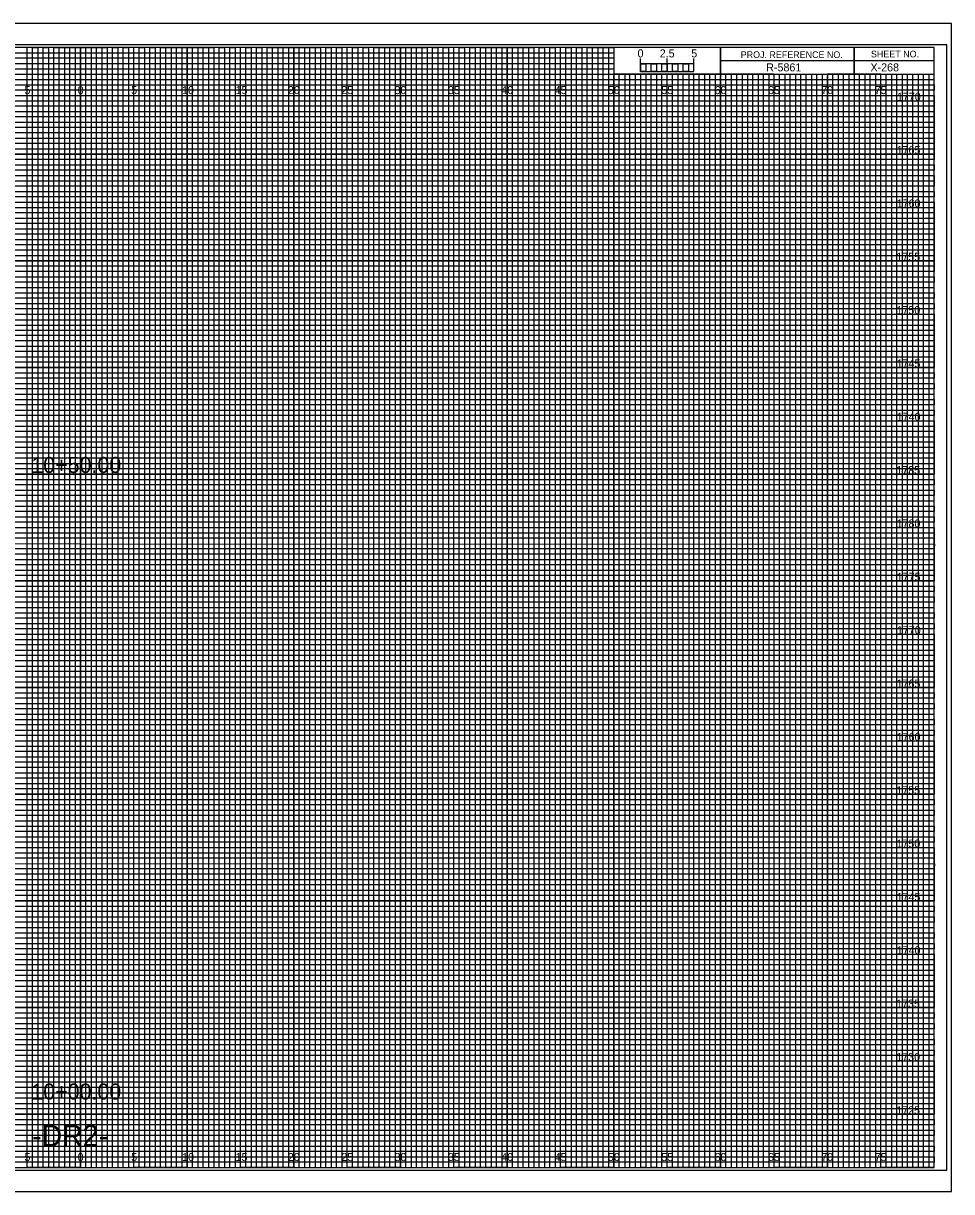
# Model space of a CAD drawing. Extents: x -7 to 162, y -2 to 217.
# Drawn here: x 74.6 to 161.7, y -2.3 to 107.3 of the extents above; entities that cross this region are included whole.
import ezdxf

# ---------------------------------------------------------------- set-up
doc = ezdxf.new("R2010")
doc.units = 0
for name, color, linetype in [('Prop XS Alignment Label', 7, 'Continuous'), ('Prop XS Bar Scale Labels', 7, 'Continuous'), ('Prop XS Elevation Labels', 7, 'Continuous'), ('Prop XS Offset Labels', 7, 'Continuous'), ('Prop XS Project Number', 7, 'Continuous'), ('Prop XS Sheet Number', 7, 'Continuous'), ('Prop XS Station Labels', 7, 'Continuous'), ('Sheet Cross Section CELL', 7, 'Continuous'), ('Sheet Cross Section Grid Major CELL', 7, 'Continuous'), ('Sheet Cross Section Grid Middle CELL', 7, 'Continuous'), ('Sheet Cross Section Grid Minor 1 CELL', 7, 'Continuous'), ('Sheet Cross Section Grid Minor 2 CELL', 7, 'Continuous'), ('Sheet Cross Section Scale CELL', 7, 'Continuous'), ('Sheet Cutting Line CELL', 7, 'Continuous'), ('Sheet DOT Grid CELL', 7, 'Continuous'), ('Sheet Plot Border Inside CELL', 7, 'Continuous'), ('Sheet Plot Border Outside CELL', 7, 'Continuous')]:
    doc.layers.add(name, color=color, linetype=linetype)

msp = doc.modelspace()

# ---------------------------------------------------------------- linework, layer by layer
at = {"layer": 'Sheet Cross Section CELL'}
for p, q in [((152.5, 105), (152.5, 102.5)), ((152.5, 102.5), (152.5, 105)), ((160, 103.75), (140, 103.75)), ((140, 103.75), (140, 102.5)), ((140, 102.5), (160, 102.5))]:
    msp.add_line(p, q, dxfattribs=at)
for points in [[(160, 105), (0, 105), (0, 0), (160, 0)], [(140, 105), (130, 105), (130, 102.52), (140, 102.52)], [(160, 105), (140, 105), (140, 102.5), (160, 102.5)]]:
    msp.add_lwpolyline(points, close=True, dxfattribs=at)
at = {"layer": 'Sheet Cross Section Grid Major CELL'}
for p, q in [((75, 105), (70, 105)), ((75, 0), (75, 105)), ((85, 105), (80, 105)), ((80, 105), (80, 0)), ((85, 0), (85, 105)), ((95, 105), (90, 105)), ((90, 105), (90, 0)), ((95, 0), (95, 105)), ((105, 105), (100, 105)), ((100, 105), (100, 0)), ((105, 0), (105, 105)), ((115, 105), (110, 105)), ((110, 105), (110, 0)), ((115, 0), (115, 105)), ((125, 105), (120, 105)), ((120, 105), (120, 0)), ((125, 0), (125, 105)), ((130, 105), (130, 0)), ((135, 0), (135, 102.5)), ((145, 102.5), (140, 102.5)), ((140, 102.5), (140, 0)), ((145, 0), (145, 102.5)), ((155, 102.5), (150, 102.5)), ((150, 102.5), (150, 0)), ((155, 0), (155, 102.5)), ((80, 0), (75, 0)), ((90, 0), (85, 0)), ((100, 0), (95, 0)), ((110, 0), (105, 0)), ((120, 0), (115, 0)), ((130, 0), (125, 0)), ((140, 0), (135, 0)), ((150, 0), (145, 0)), ((160, 0), (155, 0)), ((160, 0), (160, 0))]:
    msp.add_line(p, q, dxfattribs=at)
for points in [[(0, 100), (160, 100), (160, 95), (0, 95)], [(0, 90), (160, 90), (160, 85), (0, 85)], [(0, 80), (160, 80), (160, 75), (0, 75)], [(0, 70), (160, 70), (160, 65), (0, 65)], [(0, 60), (160, 60), (160, 55), (0, 55)], [(0, 50), (160, 50), (160, 45), (0, 45)], [(0, 40), (160, 40), (160, 35), (0, 35)], [(0, 30), (160, 30), (160, 25), (0, 25)], [(0, 20), (160, 20), (160, 15), (0, 15)], [(0, 10), (160, 10), (160, 5), (0, 5)]]:
    msp.add_lwpolyline(points, dxfattribs=at)
at = {"layer": 'Sheet Cross Section Grid Middle CELL'}
for points in [[(72.5, 0), (77.5, 0), (77.5, 105), (82.5, 105), (82.5, 0), (87.5, 0), (87.5, 105), (92.5, 105), (92.5, 0), (97.5, 0), (97.5, 105), (102.5, 105), (102.5, 0), (107.5, 0), (107.5, 105), (112.5, 105), (112.5, 0), (117.5, 0), (117.5, 105), (122.5, 105), (122.5, 0), (127.5, 0), (127.5, 105), (129.97, 105), (130, 105), (130, 102.5), (132.5, 102.5), (132.5, 0), (137.5, 0), (137.5, 102.5), (142.5, 102.5), (142.5, 0), (147.5, 0), (147.5, 102.5), (152.5, 102.5), (152.5, 0), (157.5, 0), (157.5, 102.5)], [(0, 102.5), (137.5, 102.5)], [(0, 92.5), (160, 92.5), (160, 97.5), (0, 97.5)], [(0, 82.5), (160, 82.5), (160, 87.5), (0, 87.5)], [(0, 72.5), (160, 72.5), (160, 77.5), (0, 77.5)], [(0, 62.5), (160, 62.5), (160, 67.5), (0, 67.5)], [(0, 52.5), (160, 52.5), (160, 57.5), (0, 57.5)], [(0, 42.5), (160, 42.5), (160, 47.5), (0, 47.5)], [(0, 32.5), (160, 32.5), (160, 37.5), (0, 37.5)], [(0, 22.5), (160, 22.5), (160, 27.5), (0, 27.5)], [(0, 12.5), (160, 12.5), (160, 17.5), (0, 17.5)], [(0, 2.5), (160, 2.5), (160, 7.5), (0, 7.5)]]:
    msp.add_lwpolyline(points, dxfattribs=at)
at = {"layer": 'Sheet Cross Section Grid Minor 1 CELL'}
for p, q in [((0, 104.5), (130, 104.5)), ((130, 104.5), (130, 103.99)), ((130, 103.99), (0, 103.99)), ((0, 103.5), (130, 103.5)), ((130, 102.95), (0, 102.95)), ((130, 103.5), (130, 102.95)), ((0, 102), (160, 102))]:
    msp.add_line(p, q, dxfattribs=at)
for points in [[(0, 101.5), (135, 101.5), (160, 101.5), (160, 101), (0, 101)], [(0, 100.5), (160, 100.5), (160, 99.5), (0, 99.5)], [(0, 99), (160, 99), (160, 98.5), (0, 98.49)], [(0, 98), (160, 98), (160, 97), (0, 97)], [(0, 96.5), (160, 96.5), (160, 96), (0, 96)], [(0, 95.5), (160, 95.5), (160, 94.5), (0, 94.5)], [(0, 94), (160, 94), (160, 93.5), (0, 93.5)], [(0, 93), (160, 93), (160, 92), (0, 92)], [(0, 91.5), (160, 91.5), (160, 91), (0, 91)], [(0, 90.5), (160, 90.5), (160, 89.5), (0, 89.5)], [(0, 89), (160, 89), (160, 88.5), (0, 88.5)], [(0, 88), (160, 88), (160, 86.98), (160, 86.5), (160, 86), (0, 86)], [(0, 87), (160, 87), (160, 86.5), (0, 86.5)], [(0, 85.5), (160, 85.5), (160, 84.5), (0, 84.52)], [(0, 84.52), (160, 84.5), (160, 84), (0, 84)], [(0, 83.5), (160, 83.5), (160, 83), (0, 83)], [(0, 82), (160, 82), (160, 81.5), (0, 81.5)], [(0, 81), (160, 81), (160, 80.5), (0, 80.5)], [(-0.04, 79.45), (160, 79.45), (160, 78.94), (-0.04, 78.94)], [(0, 78.5), (160, 78.5), (160, 78), (0, 78)], [(0, 77), (160, 77), (160, 76.5), (0, 76.5)], [(0, 76), (160, 76), (160, 75.5), (0, 75.5)], [(0, 74.5), (160, 74.5), (160, 74), (0, 74)], [(0, 73.5), (160, 73.5), (160, 73), (0, 73)], [(0, 72), (160, 72), (160, 71.5), (0, 71.5)], [(0, 71), (160, 71), (160, 70.5), (0, 70.5)], [(0, 69.5), (160, 69.5), (160, 68.99), (0, 69)], [(0, 68.5), (160, 68.5), (160, 68), (0, 68)], [(0, 67), (160, 67), (160, 66.5), (0, 66.5)], [(0, 66), (160, 66), (160, 65.5), (0, 65.5)], [(0, 64.5), (160, 64.5), (160, 64), (0, 64)], [(0, 63.5), (160, 63.5), (160, 63), (0, 63)], [(0, 62), (160, 62), (160, 61.5), (0, 61.5)], [(0, 61), (160, 61), (160, 60.5), (0, 60.5)], [(0, 59.5), (160, 59.5), (160, 59), (0, 59)], [(0, 58.5), (160.03, 58.45), (160, 58), (0, 58)], [(0, 57), (160, 57), (160, 56.5), (0, 56.5)], [(0, 56), (160, 56), (160, 55.5), (0, 55.5)], [(0, 54.5), (160, 54.5), (160, 54), (0, 54)], [(0, 53.5), (160, 53.5), (160, 53), (0, 53)], [(0, 52), (160, 52), (160, 51.5), (0, 51.5)], [(0, 51), (160, 51), (160, 50.5), (0, 50.5)], [(0, 49.5), (160, 49.5), (160, 49), (0, 49)], [(0, 48.5), (160, 48.5), (160, 48), (0, 48)], [(0, 47), (160, 47), (160, 46.5), (0, 46.5)], [(0, 46), (160, 46), (160, 45.5), (0, 45.5)], [(0, 44.5), (160, 44.5), (160, 44), (0, 44)], [(0, 43.5), (160, 43.5), (160, 43), (0, 43)], [(0, 42), (160, 42), (160, 41.5), (0, 41.5)], [(0, 41), (160, 41), (160, 40.5), (0, 40.5)], [(0, 39.5), (160, 39.5), (160, 38.99), (0, 39)], [(0, 38.5), (160, 38.5), (160, 38), (0, 38)], [(0, 37), (160, 37), (160, 36.5), (0, 36.5)], [(0, 36), (160, 36), (160, 35.5), (0, 35.5)], [(0, 34.5), (160, 34.5), (160, 34), (0, 34)], [(0, 33.5), (160, 33.5), (160, 33), (0, 33)], [(0, 32), (160, 32), (160, 31.5), (0, 31.5)], [(0, 31), (160, 31), (160, 30.5), (0, 30.5)], [(0, 29.5), (160, 29.5), (160, 29), (0, 29)], [(0, 28.5), (160.03, 28.46), (160, 28), (0, 28)], [(0, 27), (160, 27), (160, 26.5), (0, 26.5)], [(0, 26), (160, 26), (160, 25.5), (0, 25.5)], [(0, 24.5), (160, 24.5), (160, 24), (0, 24)], [(0, 23.5), (160, 23.5), (160, 23), (0, 23)], [(0, 22), (160, 22), (160, 21.5), (0, 21.5)], [(0, 21), (160, 21), (160, 20.5), (0, 20.5)], [(0, 19.5), (160, 19.5), (160, 19), (0, 19)], [(0, 18.5), (160, 18.5), (160, 18), (0, 18)], [(0, 17), (160, 17), (160, 16.5), (0, 16.5)], [(0, 16), (160, 16), (160, 15.5), (0, 15.5)], [(0, 14.5), (160, 14.5), (160, 14), (0, 14)], [(0, 13.5), (160, 13.5), (160, 13), (0, 13)], [(0, 12), (160, 12), (160, 11.5), (0, 11.5)], [(0, 11), (160, 11), (160, 10.5), (0, 10.5)], [(0, 9.5), (160, 9.5), (160, 9), (0, 9)], [(0, 8.5), (160, 8.5), (160, 8), (0, 8)], [(0, 7), (160, 7), (160, 6.5), (0, 6.5)], [(0, 6), (160, 6), (160, 5.5), (0, 5.5)], [(0, 4.5), (160, 4.5), (160, 4), (0, 4)], [(0, 3.5), (160, 3.5), (160, 3), (0, 3)], [(0, 2), (160, 2), (160, 1.5), (0, 1.5)], [(0, 1), (160, 1), (160, 0.5), (0, 0.5)]]:
    msp.add_lwpolyline(points, dxfattribs=at)
at = {"layer": 'Sheet Cross Section Grid Minor 2 CELL'}
for p, q in [((133.5, 102.5), (133, 102.5)), ((133, 102.5), (133, 0)), ((133.5, 0), (133.5, 102.5)), ((134.5, 102.5), (134, 102.5)), ((134, 102.5), (134, 0)), ((134.5, 0), (134.5, 102.5)), ((133, 0), (132.5, 0)), ((134, 0), (133.5, 0))]:
    msp.add_line(p, q, dxfattribs=at)
for points in [[(75, 0), (75.5, 0), (75.5, 105), (76, 105), (76, 0)], [(76, 0), (76.5, 0), (76.5, 105), (77, 105), (77, 0)], [(77.5, 0), (78, 0), (78, 105), (78.5, 105), (78.5, 0)], [(78.5, 0), (79, 0), (79, 105), (79.5, 105), (79.5, 0)], [(80, 0), (80.5, 0), (80.5, 105), (81, 105), (81, 0)], [(81, 0), (81.5, 0), (81.5, 105), (82, 105), (82, 0)], [(82.5, 0), (83, 0), (83, 105), (83.5, 105), (83.5, 0)], [(83.5, 0), (84, 0), (84, 105), (84.5, 105), (84.5, 0)], [(85, 0), (85.5, 0), (85.5, 105), (86, 105), (86, 0)], [(86, 0), (86.5, 0), (86.5, 105), (87, 105), (87, 0)], [(87.5, 0), (88, 0), (88, 105), (88.5, 105), (88.5, 0)], [(88.5, 0), (89, 0), (89, 105), (89.5, 105), (89.5, 0)], [(90, 0), (90.5, 0), (90.5, 105), (91, 105), (91, 0)], [(91, 0), (91.5, 0), (91.5, 105), (92, 105), (92, 0)], [(92.5, 0), (93, 0), (93, 105), (93.5, 105), (93.5, 0)], [(93.5, 0), (94, 0), (94, 105), (94.5, 105), (94.5, 0)], [(95, 0), (95.5, 0), (95.5, 105), (96, 105), (96, 0)], [(96, 0), (96.5, 0), (96.5, 105), (97, 105), (97, 0)], [(97.5, 0), (98, 0), (98, 105), (98.5, 105), (98.5, 0)], [(98.5, 0), (99, 0), (99, 105), (99.5, 105), (99.5, 0)], [(100, 0), (100.5, 0), (100.5, 105), (101, 105), (101, 0)], [(101, 0), (101.5, 0), (101.5, 105), (102, 105), (102, 0)], [(102.5, 0), (103, 0), (103, 105), (103.5, 105), (103.5, 0)], [(103.5, 0), (104, 0), (104, 105), (104.5, 105), (104.5, 0)], [(105, 0), (105.5, 0), (105.5, 105), (106, 105), (106, 0)], [(106, 0), (106.5, 0), (106.5, 105), (107, 105), (107, 0)], [(107.5, 0), (108, 0), (108, 105), (108.5, 105), (108.5, 0)], [(108.5, 0), (109, 0), (109, 105), (109.5, 105), (109.5, 0)], [(110, 0), (110.5, 0), (110.5, 105), (111, 105), (111, 0)], [(111, 0), (111.5, 0), (111.5, 105), (112, 105), (112, 0)], [(112.5, 0), (113, 0), (113, 105), (113.5, 105), (113.5, 0)], [(113.5, 0), (114, 0), (114, 105), (114.5, 105), (114.5, 0)], [(115, 0), (115.5, 0), (115.5, 105), (116, 105), (116, 0)], [(116, 0), (116.5, 0), (116.5, 105), (117, 105), (117, 0)], [(117.5, 0), (118, 0), (118, 105), (118.5, 105), (118.5, 0)], [(118.5, 0), (119, 0), (119, 105), (119.5, 105), (119.5, 0)], [(120, 0), (120.5, 0), (120.5, 105), (121, 105), (121, 0)], [(121, 0), (121.5, 0), (121.5, 105), (122, 105), (122, 0)], [(122.5, 0), (123, 0), (123, 105), (123.5, 105), (123.5, 0)], [(123.5, 0), (124, 0), (124, 105), (124.5, 105), (124.5, 0)], [(125, 0), (125.5, 0), (125.5, 105), (126, 105), (126, 0)], [(126, 0), (126.5, 0), (126.5, 105), (127, 105), (127, 0)], [(127.5, 0), (128, 0), (128, 105), (128.5, 105), (128.5, 0)], [(128.5, 0), (129, 0), (129, 105), (129.5, 105), (129.5, 0)], [(130, 0), (130.5, 0), (130.5, 102.5), (131.01, 102.5), (131.01, 0)], [(131, 0), (131.5, 0), (131.5, 102.5), (132, 102.5), (132, 0)], [(135, 0), (135.49, 0), (135.49, 102.5), (136, 102.5), (136, 0)], [(136, 0), (136.5, 0), (136.5, 102.5), (137.03, 102.5), (137.03, 0)], [(137.5, 0), (138, 0), (138, 102.5), (138.5, 102.5), (138.5, 0)], [(138.5, 0), (139, 0), (139, 102.5), (139.5, 102.5), (139.5, 0)], [(140, 0), (140.5, 0), (140.5, 102.5), (141, 102.5), (141, 0)], [(141, 0), (141.5, 0), (141.5, 102.5), (142, 102.5), (142, 0)], [(142.5, 0), (143, 0), (143, 102.5), (143.5, 102.5), (143.5, 0)], [(143.5, 0), (144, 0), (144, 102.5), (144.5, 102.5), (144.5, 0)], [(145, 0), (145.5, 0), (145.5, 102.5), (146, 102.5), (146, 0)], [(146, 0), (146.5, 0), (146.5, 102.5), (147, 102.5), (147, 0)], [(147.5, 0), (148, 0), (148, 102.5), (148.5, 102.5), (148.5, 0)], [(148.5, 0), (149, 0), (149, 102.5), (149.5, 102.5), (149.5, 0)], [(150, 0), (150.5, 0), (150.5, 102.5), (151, 102.5), (151, 0)], [(151, 0), (151.5, 0), (151.5, 102.5), (152, 102.5), (152, 0)], [(152.5, 0), (153, 0), (153, 102.5), (153.5, 102.5), (153.5, 0)], [(153.5, 0), (154, 0), (154, 102.5), (154.5, 102.5), (154.5, 0)], [(155, 0), (155.5, 0), (155.5, 102.5), (156, 102.5), (156, 0)], [(156, 0), (156.5, 0), (156.5, 102.5), (157, 102.5), (157, 0)], [(157.5, 0), (158, 0), (158, 102.5), (158.5, 102.5), (158.5, 0)], [(158.5, 0), (159, 0), (159, 102.5), (159.5, 102.5), (159.5, 0)]]:
    msp.add_lwpolyline(points, dxfattribs=at)
at = {"layer": 'Sheet Cross Section Scale CELL'}
for p, q in [((132.5, 102.75), (132.5, 103.95)), ((132.5, 103.45), (132.5, 103.95)), ((135, 102.75), (135, 103.95)), ((137.5, 102.75), (137.5, 103.95)), ((137.5, 103.45), (137.5, 103.95))]:
    msp.add_line(p, q, dxfattribs=at)
for points in [[(137.5, 103.45), (132.5, 103.45), (132.5, 102.75), (137.5, 102.75)], [(132.5, 103.45), (133, 103.45), (133, 102.75), (132.5, 102.75)], [(133.5, 103.45), (134, 103.45), (134, 102.75), (133.5, 102.75)], [(134.5, 103.45), (135, 103.45), (135, 102.75), (134.5, 102.75)], [(135.5, 103.45), (136, 103.45), (136, 102.75), (135.5, 102.75)], [(136.5, 103.45), (137, 103.45), (137, 102.75), (136.5, 102.75)]]:
    msp.add_lwpolyline(points, close=True, dxfattribs=at)
at = {"layer": 'Sheet Cutting Line CELL'}
for p, q in [((161.65, 107.25), (-6.7, 107.25)), ((-6.7, -2.25), (161.65, -2.25))]:
    msp.add_line(p, q, dxfattribs=at)
at = {"layer": 'Sheet DOT Grid CELL'}
for p, q in [((75, 0), (75, 105)), ((80, 0), (80, 105)), ((85, 0), (85, 105)), ((90, 0), (90, 105)), ((95, 0), (95, 105)), ((100, 0), (100, 105)), ((105, 0), (105, 105)), ((110, 0), (110, 105)), ((115, 0), (115, 105)), ((120, 0), (120, 105)), ((125, 0), (125, 105)), ((130, 0), (130, 102.34)), ((135, 0), (135, 102.34)), ((140, 0), (140, 102.34)), ((145, 0), (145, 102.34)), ((150, 0), (150, 102.34)), ((155, 0), (155, 102.34)), ((0, 100), (160, 100)), ((0, 95), (160, 95)), ((0, 90), (160, 90)), ((0, 85), (160, 85)), ((0, 80), (160, 80)), ((0, 75), (160, 75)), ((0, 70), (160, 70)), ((0, 65), (160, 65)), ((0, 60), (160, 60)), ((0, 55), (160, 55)), ((0, 50), (160, 50)), ((0, 45), (160, 45)), ((0, 40), (160, 40)), ((0, 35), (160, 35)), ((0, 30), (160, 30)), ((0, 25), (160, 25)), ((0, 20), (160, 20)), ((0, 15), (160, 15)), ((0, 10), (160, 10)), ((0, 5), (160, 5))]:
    msp.add_line(p, q, dxfattribs=at)
at = {"layer": 'Sheet Plot Border Inside CELL'}
msp.add_lwpolyline([(-5.4, -0.25), (161.2, -0.25), (161.2, 105.25), (-5.4, 105.25)], close=True, dxfattribs=at)
at = {"layer": 'Sheet Plot Border Outside CELL'}
msp.add_lwpolyline([(-6.7, -2.25), (161.65, -2.25), (161.65, 107.25), (-6.7, 107.25)], close=True, dxfattribs=at)

# ---------------------------------------------------------------- texts
at = {"layer": 'Prop XS Alignment Label'}
msp.add_text('-DR2-', height=2, dxfattribs=at).set_placement((75.45, 2))
at = {"layer": 'Prop XS Bar Scale Labels'}
for s, p in [('2.5', (134.29, 104.06)), ('5', (137.24, 104.06))]:
    msp.add_text(s, height=0.75, dxfattribs=at).set_placement(p)
at = {"layer": 'Prop XS Elevation Labels'}
for s, p in [('1770', (156.52, 100)), ('1765', (156.49, 95)), ('1760', (156.5, 90)), ('1755', (156.47, 85)), ('1750', (156.48, 80)), ('1745', (156.49, 75)), ('1740', (156.5, 70)), ('1735', (156.45, 65)), ('1785', (156.48, 65)), ('1780', (156.49, 60)), ('1775', (156.51, 55)), ('1770', (156.52, 50)), ('1765', (156.49, 45)), ('1760', (156.5, 40)), ('1755', (156.47, 35)), ('1750', (156.48, 30)), ('1745', (156.49, 25)), ('1740', (156.5, 20)), ('1735', (156.45, 15)), ('1730', (156.46, 10)), ('1725', (156.46, 5))]:
    msp.add_text(s, height=0.75, dxfattribs=at).set_placement(p)
at = {"layer": 'Prop XS Offset Labels'}
for s, p in [('5', (74.74, 100.62)), ('0', (79.73, 100.62)), ('0', (79.73, 100.62)), ('5', (84.74, 100.62)), ('10', (89.52, 100.62)), ('15', (94.53, 100.62)), ('20', (99.43, 100.62)), ('25', (104.44, 100.62)), ('30', (109.43, 100.62)), ('35', (114.44, 100.62)), ('40', (119.43, 100.62)), ('45', (124.44, 100.62)), ('50', (129.43, 100.62)), ('55', (134.44, 100.62)), ('60', (139.43, 100.62)), ('65', (144.44, 100.62)), ('70', (149.43, 100.62)), ('75', (154.44, 100.62)), ('5', (74.74, 0.62)), ('0', (79.73, 0.62)), ('0', (79.73, 0.62)), ('5', (84.74, 0.62)), ('10', (89.52, 0.62)), ('15', (94.53, 0.62)), ('20', (99.43, 0.62)), ('25', (104.44, 0.62)), ('30', (109.43, 0.62)), ('35', (114.44, 0.62)), ('40', (119.43, 0.62)), ('45', (124.44, 0.62)), ('50', (129.43, 0.62)), ('55', (134.44, 0.62)), ('60', (139.43, 0.62)), ('65', (144.44, 0.62)), ('70', (149.43, 0.62)), ('75', (154.44, 0.62))]:
    msp.add_text(s, height=0.75, dxfattribs=at).set_placement(p)
at = {"layer": 'Prop XS Project Number'}
msp.add_text('R-5861', height=0.75, dxfattribs=at).set_placement((144.27, 102.75))
at = {"layer": 'Prop XS Sheet Number'}
msp.add_text('X-268', height=0.75, dxfattribs=at).set_placement((154.04, 102.75))
at = {"layer": 'Prop XS Station Labels'}
for s, p in [('10+50.00', (75.39, 65.11)), ('10+00.00', (75.39, 6.38))]:
    msp.add_text(s, height=1.5, dxfattribs=at).set_placement(p)
at = {"layer": 'Sheet Cross Section CELL'}
for s, p in [('PROJ. REFERENCE NO.', (141.88, 104)), ('SHEET NO.', (154.09, 104.06))]:
    msp.add_text(s, height=0.625, dxfattribs=at).set_placement(p)
at = {"layer": 'Sheet Cross Section Scale CELL'}
msp.add_text('0', height=0.75, dxfattribs=at).set_placement((132.21, 104.06))

doc.saveas('drawing.dxf')
